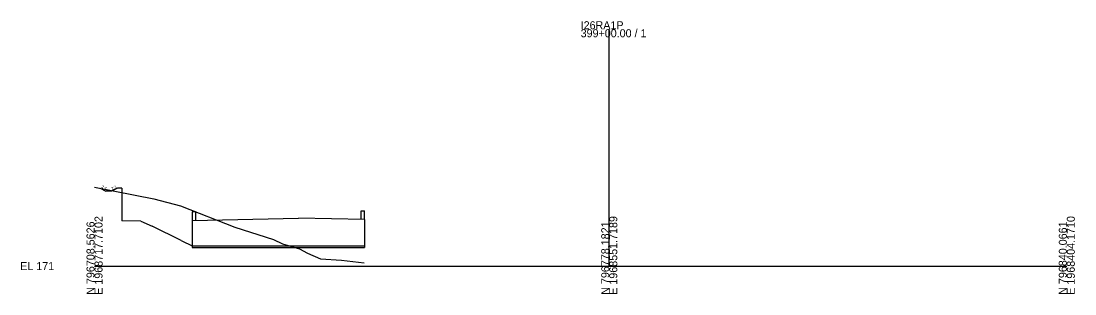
# Model space of a CAD drawing. Extents: x -2696 to 1968732, y 5067 to 796742.
import ezdxf

# ---------------------------------------------------------------- set-up
doc = ezdxf.new("R2010")
doc.units = 0
for name, color, linetype in [('BR_AUTO DIMENSION', 7, 'Continuous'), ('BR_BORDER LINES', 7, 'Continuous'), ('RD_PD_GR', 7, 'Continuous'), ('RD_PD_WallFill', 7, 'Continuous'), ('RD_TX_TypSect', 7, 'Continuous'), ('RD_XS_EarthShd', 7, 'Continuous')]:
    doc.layers.add(name, color=color, linetype=linetype)

msp = doc.modelspace()

# ---------------------------------------------------------------- linework, layer by layer
at = {"layer": 'BR_AUTO DIMENSION'}
for p, q in [((-2490.4, 5076.8), (-2490.4, 5159.52)), ((-2670.4, 5076.8), (-2490.4, 5076.8)), ((-2490.4, 5076.8), (-2330.4, 5076.8))]:
    msp.add_line(p, q, dxfattribs=at)
at = {"layer": 'BR_BORDER LINES'}
msp.add_lwpolyline([(-2670.4, 5104.38), (-2649.65, 5100.34), (-2640.35, 5097.91), (-2621.33, 5090.43), (-2607.82, 5086.05), (-2604.67, 5084.62), (-2598.71, 5082.88), (-2595.88, 5081.3), (-2591.42, 5079.41), (-2584.02, 5078.89), (-2576.1, 5078.01)], dxfattribs=at)
at = {"layer": 'RD_PD_GR'}
for p, q in [((-2636.24, 5095.8), (-2636.24, 5092.78)), ((-2635.11, 5095.8), (-2636.24, 5095.8)), ((-2636.24, 5092.78), (-2599.11, 5093.52)), ((-2635.11, 5095.8), (-2635.11, 5092.8)), ((-2575.99, 5093.06), (-2599.11, 5093.52)), ((-2577.11, 5093.08), (-2577.11, 5096.08)), ((-2577.11, 5096.08), (-2575.99, 5096.08)), ((-2575.99, 5093.06), (-2575.99, 5096.08)), ((-2636.24, 5092.78), (-2636.24, 5083.28)), ((-2575.99, 5093.06), (-2575.99, 5083.28)), ((-2636.24, 5083.28), (-2575.99, 5083.28)), ((-2575.99, 5083.8), (-2636.07, 5083.8))]:
    msp.add_line(p, q, dxfattribs=at)
at = {"layer": 'RD_PD_WallFill'}
for p, q in [((-2668.41, 5103.99), (-2666.41, 5102.99)), ((-2664.41, 5102.99), (-2666.41, 5102.99)), ((-2662.41, 5103.99), (-2664.41, 5102.99)), ((-2660.91, 5103.99), (-2662.41, 5103.99)), ((-2654.16, 5092.52), (-2660.91, 5092.65)), ((-2654.16, 5092.52), (-2650.26, 5090.8)), ((-2640.13, 5085.8), (-2650.26, 5090.8)), ((-2640.13, 5085.8), (-2636.07, 5083.8))]:
    msp.add_line(p, q, dxfattribs=at)
at = {"layer": 'RD_XS_EarthShd'}
msp.add_line((-2660.91, 5103.99), (-2660.91, 5092.65), dxfattribs=at)

# ---------------------------------------------------------------- texts
at = {"layer": 'BR_AUTO DIMENSION'}
for s, p in [('399+00.00 / 1', (-2500.4, 5156.72)), ('I26RA1P', (-2500.4, 5159.52)), ('EL 171', (-2696.4, 5075.4))]:
    msp.add_text(s, height=2.8, dxfattribs=at).set_placement(p)
for s, p in [('E 1968717.7102', (-2667.6, 5066.8)), ('E 1968551.7189', (-2487.6, 5066.8)), ('E 1968404.1710', (-2327.6, 5066.8)), ('N 796708.5626', (-2670.4, 5066.8)), ('N 796778.1821', (-2490.4, 5066.8)), ('N 796840.0661', (-2330.4, 5066.8))]:
    msp.add_text(s, height=2.8, rotation=90, dxfattribs=at).set_placement(p)
at = {"layer": 'RD_TX_TypSect'}
for rotation, p in [(333.4349, (-2668.1, 5104.21)), (26.5651, (-2664.22, 5103.37))]:
    msp.add_text('2:1', height=1, rotation=rotation, dxfattribs=at).set_placement(p)

doc.saveas('drawing.dxf')
